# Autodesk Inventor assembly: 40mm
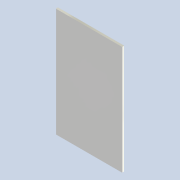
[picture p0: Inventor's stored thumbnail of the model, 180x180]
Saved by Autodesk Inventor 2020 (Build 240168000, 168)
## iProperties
Created: 2020-11
Part Number: 40mm
Document SubType Name: Assembly
Designer: Yolande
Author: Yolande
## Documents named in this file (2)
- D:\Drawing Division\3. Revit Family Files\1. White Mineral\40mm.iam
- D:\Drawing Division\3. Revit Family Files\1. White Mineral\Lambdaboard 40mm Mineral White.ipt
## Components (1 placed, 1 different names)
1. Lambdaboard 40mm Mineral White:1
